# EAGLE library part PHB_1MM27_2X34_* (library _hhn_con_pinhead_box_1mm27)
Pin Header Box-Type, 1.27mm/0.5"/50mil Pitch, 2x34 Circuits Note: see library description for an important note about THT-version
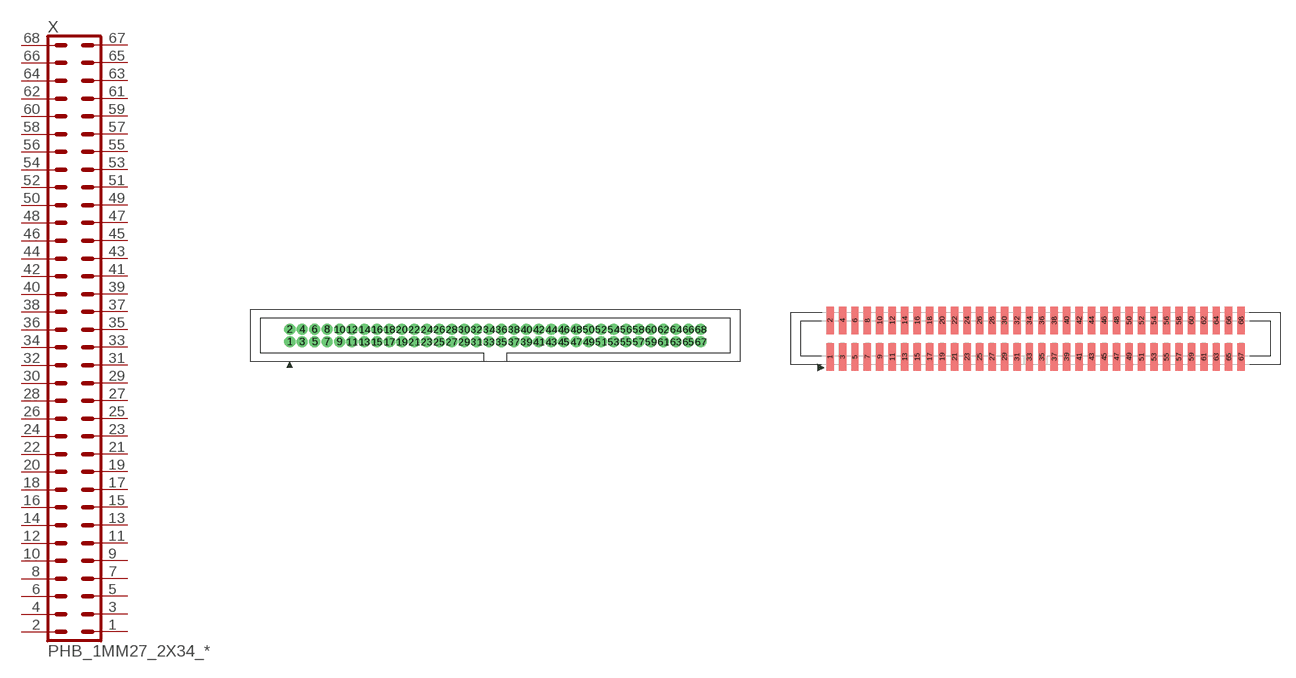
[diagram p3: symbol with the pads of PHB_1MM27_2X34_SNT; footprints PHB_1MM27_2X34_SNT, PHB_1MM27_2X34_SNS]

Designator prefix X

## PHB_1MM27_2X34_SNT  [PHB_1MM27_2X34_SNT]
1  1  pas
2  2  pas
3  3  pas
4  4  pas
5  5  pas
6  6  pas
7  7  pas
8  8  pas
9  9  pas
10  10  pas
11  11  pas
12  12  pas
13  13  pas
14  14  pas
15  15  pas
16  16  pas
17  17  pas
18  18  pas
19  19  pas
20  20  pas
21  21  pas
22  22  pas
23  23  pas
24  24  pas
25  25  pas
26  26  pas
27  27  pas
28  28  pas
29  29  pas
30  30  pas
31  31  pas
32  32  pas
33  33  pas
34  34  pas
35  35  pas
36  36  pas
37  37  pas
38  38  pas
39  39  pas
40  40  pas
41  41  pas
42  42  pas
43  43  pas
44  44  pas
45  45  pas
46  46  pas
47  47  pas
48  48  pas
49  49  pas
50  50  pas
51  51  pas
52  52  pas
53  53  pas
54  54  pas
55  55  pas
56  56  pas
57  57  pas
58  58  pas
59  59  pas
60  60  pas
61  61  pas
62  62  pas
63  63  pas
64  64  pas
65  65  pas
66  66  pas
67  67  pas
68  68  pas

## PHB_1MM27_2X34_SNS  [PHB_1MM27_2X34_SNS]
Pads as for PHB_1MM27_2X34_SNT

## Footprint PHB_1MM27_2X34_SNT (pad centres in mm)
Pin Header Box-Type, 1.27mm Pitch, 2x34 circuits, Straight, No Locking, THT Important Note: Diameter in this lbr is set to a specific value (NOT 'auto' = 0), this is ignored by actual eagle versions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
drill 0.65 pad 1 round: 1 -20.955,-0.635; 2 -20.955,0.635; 3 -19.685,-0.635; 4 -19.685,0.635; 5 -18.415,-0.635; 6 -18.415,0.635; 7 -17.145,-0.635; 8 -17.145,0.635; 9 -15.875,-0.635; 10 -15.875,0.635; 11 -14.605,-0.635; 12 -14.605,0.635; 13 -13.335,-0.635; 14 -13.335,0.635; 15 -12.065,-0.635; 16 -12.065,0.635; 17 -10.795,-0.635; 18 -10.795,0.635; 19 -9.525,-0.635; 20 -9.525,0.635; 21 -8.255,-0.635; 22 -8.255,0.635; 23 -6.985,-0.635; 24 -6.985,0.635; 25 -5.715,-0.635; 26 -5.715,0.635; 27 -4.445,-0.635; 28 -4.445,0.635; 29 -3.175,-0.635; 30 -3.175,0.635; 31 -1.905,-0.635; 32 -1.905,0.635; 33 -0.635,-0.635; 34 -0.635,0.635; 35 0.635,-0.635; 36 0.635,0.635; 37 1.905,-0.635; 38 1.905,0.635; 39 3.175,-0.635; 40 3.175,0.635; 41 4.445,-0.635; 42 4.445,0.635; 43 5.715,-0.635; 44 5.715,0.635; 45 6.985,-0.635; 46 6.985,0.635; 47 8.255,-0.635; 48 8.255,0.635; 49 9.525,-0.635; 50 9.525,0.635; 51 10.795,-0.635; 52 10.795,0.635; 53 12.065,-0.635; 54 12.065,0.635; 55 13.335,-0.635; 56 13.335,0.635; 57 14.605,-0.635; 58 14.605,0.635; 59 15.875,-0.635; 60 15.875,0.635; 61 17.145,-0.635; 62 17.145,0.635; 63 18.415,-0.635; 64 18.415,0.635; 65 19.685,-0.635; 66 19.685,0.635; 67 20.955,-0.635; 68 20.955,0.635

## Footprint PHB_1MM27_2X34_SNS (pad centres in mm)
Pin Header Box-Type, 1.27mm Pitch, 2x34 circuits, Straight, No Locking, SMT
smd 0.76 x 2.8: 1 -20.955,-1.85; 2 -20.955,1.85; 3 -19.685,-1.85; 4 -19.685,1.85; 5 -18.415,-1.85; 6 -18.415,1.85; 7 -17.145,-1.85; 8 -17.145,1.85; 9 -15.875,-1.85; 10 -15.875,1.85; 11 -14.605,-1.85; 12 -14.605,1.85; 13 -13.335,-1.85; 14 -13.335,1.85; 15 -12.065,-1.85; 16 -12.065,1.85; 17 -10.795,-1.85; 18 -10.795,1.85; 19 -9.525,-1.85; 20 -9.525,1.85; 21 -8.255,-1.85; 22 -8.255,1.85; 23 -6.985,-1.85; 24 -6.985,1.85; 25 -5.715,-1.85; 26 -5.715,1.85; 27 -4.445,-1.85; 28 -4.445,1.85; 29 -3.175,-1.85; 30 -3.175,1.85; 31 -1.905,-1.85; 32 -1.905,1.85; 33 -0.635,-1.85; 34 -0.635,1.85; 35 0.635,-1.85; 36 0.635,1.85; 37 1.905,-1.85; 38 1.905,1.85; 39 3.175,-1.85; 40 3.175,1.85; 41 4.445,-1.85; 42 4.445,1.85; 43 5.715,-1.85; 44 5.715,1.85; 45 6.985,-1.85; 46 6.985,1.85; 47 8.255,-1.85; 48 8.255,1.85; 49 9.525,-1.85; 50 9.525,1.85; 51 10.795,-1.85; 52 10.795,1.85; 53 12.065,-1.85; 54 12.065,1.85; 55 13.335,-1.85; 56 13.335,1.85; 57 14.605,-1.85; 58 14.605,1.85; 59 15.875,-1.85; 60 15.875,1.85; 61 17.145,-1.85; 62 17.145,1.85; 63 18.415,-1.85; 64 18.415,1.85; 65 19.685,-1.85; 66 19.685,1.85; 67 20.955,-1.85; 68 20.955,1.85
